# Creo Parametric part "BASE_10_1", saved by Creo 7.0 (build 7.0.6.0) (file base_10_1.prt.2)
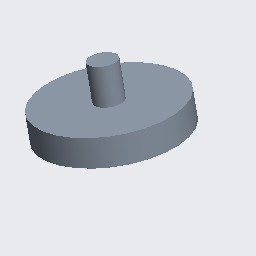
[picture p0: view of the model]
Units: millimeter Newton Second (mmNs); MM, TONNE, SECS

Created from: XX_MMNS_PART_SOLID_ABS.PRT

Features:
  1. datum plane "RIGHT"
  2. datum plane "TOP"
  3. datum plane "FRONT"
  4. coordinate system
  5. extrusion "Extrude 1"
  6. extrusion "Extrude 2"

Surfaces: 3 plane, 2 cylinder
